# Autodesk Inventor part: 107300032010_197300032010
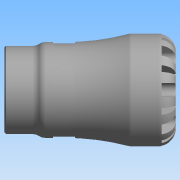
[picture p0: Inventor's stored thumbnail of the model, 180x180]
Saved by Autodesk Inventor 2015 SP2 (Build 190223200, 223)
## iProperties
Created: 2016-12
Part Number: 107300032010_197300032010
Material: Generic
Description: PLASSON FEMALE INTEGRAL BRASS THREAD 32X1" SERIES 1
Document SubType Name: Modeling
Designer: KIM
Density: 1 g/cm^3
Appearance: Default
Author: KIM
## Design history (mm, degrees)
derived "1073.ipt"
feature "Solid1::1073.ipt"
tag "TaggingFeature1"
body "Solid1"
other parameters: "d0" = 88, "d1" = 23.52, "d2" = 32, "d4" = 58, "d6" = 56, "d8" = 49.3, "d13" = 7.2, "d14" = 7.2, "d15" = 0, "d17" = 360 deg, "d19" = 8 deg, "d20" = 0.64, "d21" = 0.64, "d22" = 8 deg, "d24" = 0, "d26" = 360 deg, "d32" = 5.8, "d33" = 5.8, "d39" = 0.90873, "d42" = 30.291, "d43" = 45.24, "d46" = 2.66667, "d47" = 19, "d48" = 28.77645, "d50" = 4.29, "d51" = 0.58, "d54" = 11.2, "d55" = 7.04, "d57" = 14.112, "d58" = 0, "d68" = 360 deg, "d72" = 0.64, "d74" = 0, "d76" = 9.52, "d_" = 32, "E_" = 58, "H_" = 88, "l_" = 56, "G_" = 30.291, "l_2" = 19, "d9" = 9, "d11" = 58, "d49" = 13
